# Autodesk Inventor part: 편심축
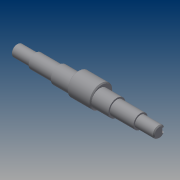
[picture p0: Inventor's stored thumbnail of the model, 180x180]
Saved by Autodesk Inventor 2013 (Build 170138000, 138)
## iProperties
Created: 2014-12
Part Number: 편심축
Material: Generic
Document SubType Name: Modeling
Designer: CAD-B28
Density: 1 g/cm^3
Author: CAD-B28
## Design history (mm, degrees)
sketch "스케치1"
  geometry: L1 (-75.5, 0)-(75.5, 0) reference; L2 (-75.5, 0)-(-75.5, 6); L3 (-75.5, 6)-(-55.5, 6); L4 (-55.5, 6)-(-55.5, 7.5); L5 (-55.5, 7.5)-(-30.5, 7.5); L6 (-30.5, 7.5)-(-30.5, 9); L7 (-30.5, 9)-(-12.5, 9); L8 (12.5, 9)-(30.5, 9); L9 (30.5, 9)-(30.5, 7.5); L10 (30.5, 7.5)-(55.5, 7.5); L11 (55.5, 7.5)-(55.5, 6); L12 (55.5, 6)-(75.5, 6); L13 (75.5, 6)-(75.5, 0); L14 (-12.5, 9)-(12.5, 9); L15 (-12.5, 2)-(12.5, 2); L16 (-12.5, 2)-(-12.5, 14); L17 (-12.5, 14)-(12.5, 14); L18 (-61.5, 6)-(-61.5, 3); L19 (-61.5, 3)-(-75.5, 3); L20 (61.5, 6)-(61.5, 3); L21 (61.5, 3)-(75.5, 3); L22 (-12.5, 2)-(12.5, 2); L23 (12.5, 14)-(12.5, 2); 1 further point
  constraints: 46 end point, 11 parallel, 7 perpendicular, 2 collinear, 2 horizontal, 2 midpoint, 2 point on line
  dimensions: "d0" = 151 distance of L1.start L1.end; "d1" = 75.5 distance of point (0, 0) L1.start; "d2" = 20 distance of L2.end L3.end; "d3" = 25 distance of L4.end L5.end; "d4" = 18 distance of L6.end L7.end; "d5" = 18 distance of L8.start L8.end; "d6" = 25 distance of L9.end L10.end; "d7" = 20 distance of L11.end L12.end; "d8" = 12 diameter of L12 L1; "d9" = 15 diameter of L10 L1; "d10" = 18 diameter of L8 L1; "d11" = 12 diameter of L3 L1; "d12" = 15 diameter of L5 L1; "d13" = 18 diameter of L7 L1; "d14" = 2 vertical distance of L1.end L15.end; "d15" = 24 diameter of L17 L15; "d16" = 3 distance of L18.start L18.end; "d17" = 14 distance of L18.end L19.end; "d18" = 3 distance of L20.start L20.end; "d19" = 14 distance of L20.end L21.end
revolve "회전1" stored, may be unused: angle "d20" = 90 deg
extrude "돌출1" cut sketch "스케치1" stored distance "d21" = 5; taper "d22" = 0 deg
revolve "회전2" stored, may be unused: angle "d23" = 90 deg
fillet "모깎기1" dims "d24" = 2.5
chamfer "모따기1" distance "d25" = 1; stored, may be unused: second distance "d26" = 2, angle "d27" = 45 deg
node "솔리드1"
